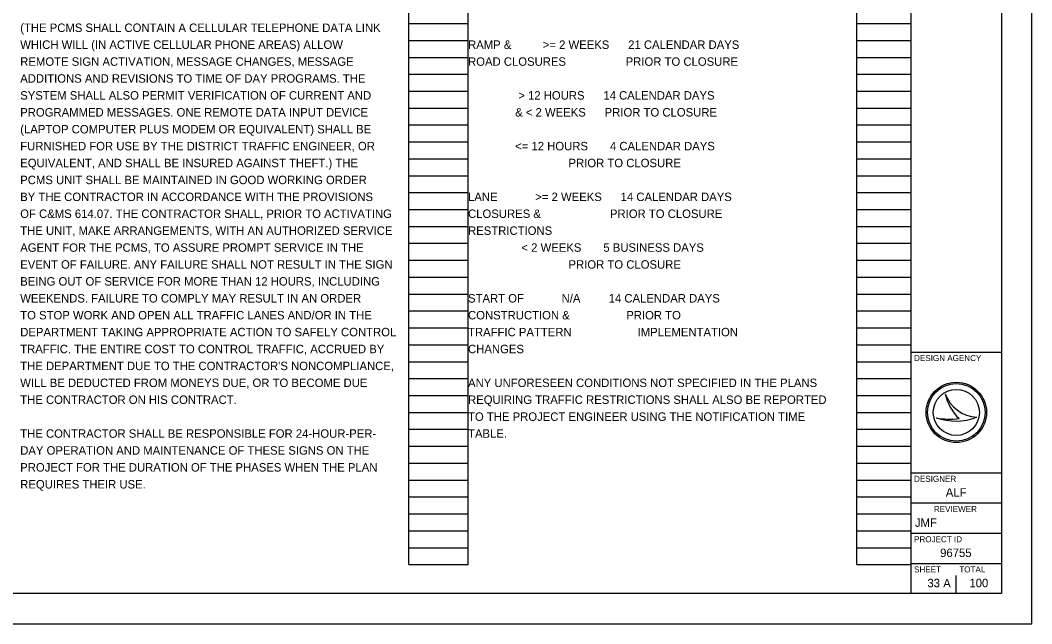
# Model space of a CAD drawing. Extents: x 0 to 34, y 0 to 22.
# Drawn here: x 17.24 to 34, y 0 to 9.99 of the extents above; entities that cross this region are included whole.
import ezdxf

# ---------------------------------------------------------------- set-up
doc = ezdxf.new("R2010")
doc.units = 0
for name, color, linetype in [('Default', 7, 'Continuous'), ('SH_Border', 7, 'Continuous'), ('SH_Cut_Line', 7, 'Continuous'), ('SH_Data', 7, 'Continuous'), ('SH_Text', 7, 'Continuous')]:
    doc.layers.add(name, color=color, linetype=linetype)

msp = doc.modelspace()

# ---------------------------------------------------------------- linework, layer by layer
at = {"layer": 'SH_Border'}
for p, q in [((32, 0.5), (32, 21.5)), ((32, 4.5), (33.5, 4.5)), ((32, 2.5), (33.5, 2.5)), ((32, 2), (33.5, 2)), ((32, 1.5), (33.5, 1.5)), ((32, 1), (33.5, 1))]:
    msp.add_line(p, q, dxfattribs=at)
msp.add_lwpolyline([(1.5, 21.5), (33.5, 21.5), (33.5, 0.5), (1.5, 0.5)], close=True, dxfattribs=at)
at = {"layer": 'SH_Cut_Line'}
msp.add_lwpolyline([(0, 0), (34, 0), (34, 22), (0, 22)], close=True, dxfattribs=at)
at = {"layer": 'SH_Data'}
for p, q in [((23.68, 0.98), (23.68, 21.14)), ((24.66, 0.98), (24.66, 21.14)), ((31.1, 0.98), (31.1, 21.14)), ((32, 0.98), (32, 21.14)), ((23.68, 9.94), (24.66, 9.94)), ((31.1, 9.94), (32, 9.94)), ((23.68, 9.66), (24.66, 9.66)), ((31.1, 9.66), (32, 9.66)), ((23.68, 9.38), (24.66, 9.38)), ((31.1, 9.38), (32, 9.38)), ((23.68, 9.1), (24.66, 9.1)), ((31.1, 9.1), (32, 9.1)), ((23.68, 8.82), (24.66, 8.82)), ((31.1, 8.82), (32, 8.82)), ((23.68, 8.54), (24.66, 8.54)), ((31.1, 8.54), (32, 8.54)), ((23.68, 8.26), (24.66, 8.26)), ((31.1, 8.26), (32, 8.26)), ((23.68, 7.98), (24.66, 7.98)), ((31.1, 7.98), (32, 7.98)), ((23.68, 7.7), (24.66, 7.7)), ((31.1, 7.7), (32, 7.7)), ((23.68, 7.42), (24.66, 7.42)), ((31.1, 7.42), (32, 7.42)), ((23.68, 7.14), (24.66, 7.14)), ((31.1, 7.14), (32, 7.14)), ((23.68, 6.86), (24.66, 6.86)), ((31.1, 6.86), (32, 6.86)), ((23.68, 6.58), (24.66, 6.58)), ((31.1, 6.58), (32, 6.58)), ((23.68, 6.3), (24.66, 6.3)), ((31.1, 6.3), (32, 6.3)), ((23.68, 6.02), (24.66, 6.02)), ((31.1, 6.02), (32, 6.02)), ((23.68, 5.74), (24.66, 5.74)), ((31.1, 5.74), (32, 5.74)), ((23.68, 5.46), (24.66, 5.46)), ((31.1, 5.46), (32, 5.46)), ((23.68, 5.18), (24.66, 5.18)), ((31.1, 5.18), (32, 5.18)), ((23.68, 4.9), (24.66, 4.9)), ((31.1, 4.9), (32, 4.9)), ((23.68, 4.62), (24.66, 4.62)), ((31.1, 4.62), (32, 4.62)), ((23.68, 4.34), (24.66, 4.34)), ((31.1, 4.34), (32, 4.34)), ((23.68, 4.06), (24.66, 4.06)), ((31.1, 4.06), (32, 4.06)), ((23.68, 3.78), (24.66, 3.78)), ((31.1, 3.78), (32, 3.78)), ((32.567, 3.81), (32.567, 3.81)), ((23.68, 3.5), (24.66, 3.5)), ((31.1, 3.5), (32, 3.5)), ((32.417, 3.41), (32.417, 3.41)), ((32.75, 3.5), (32.75, 3.5)), ((33.087, 3.419), (33.087, 3.419)), ((23.68, 3.22), (24.66, 3.22)), ((31.1, 3.22), (32, 3.22)), ((23.68, 2.94), (24.66, 2.94)), ((31.1, 2.94), (32, 2.94)), ((23.68, 2.66), (24.66, 2.66)), ((31.1, 2.66), (32, 2.66)), ((23.68, 2.38), (24.66, 2.38)), ((31.1, 2.38), (32, 2.38)), ((23.68, 2.1), (24.66, 2.1)), ((31.1, 2.1), (32, 2.1)), ((23.68, 1.82), (24.66, 1.82)), ((31.1, 1.82), (32, 1.82)), ((23.68, 1.54), (24.66, 1.54)), ((31.1, 1.54), (32, 1.54)), ((23.68, 1.26), (24.66, 1.26)), ((31.1, 1.26), (32, 1.26)), ((23.68, 0.98), (24.66, 0.98)), ((31.1, 0.98), (32, 0.98)), ((32.375, 0.675), (32.375, 0.675)), ((32.75, 0.5), (32.75, 0.8))]:
    msp.add_line(p, q, dxfattribs=at)
for radius in [0.5, 0.477, 0.477, 0.382]:
    msp.add_circle((32.75, 3.5), radius, dxfattribs=at)
for centre, radius, start, end in [((33.116, 3.998), 0.58, 198.9257, 198.9319), ((33.347, 3.97), 0.796, 191.6379, 191.6421), ((33.116, 3.998), 0.58, 198.9319, 267.1657), ((33.347, 3.97), 0.796, 191.6421, 226.0947), ((32.739, 4.37), 1.013, 251.4576, 290.0832), ((32.648, 4.654), 1.266, 259.4964, 259.4995), ((32.739, 4.37), 1.013, 251.4527, 251.4576), ((32.648, 4.654), 1.266, 259.4995, 276.6672)]:
    msp.add_arc(centre, radius, start, end, dxfattribs=at)

# ---------------------------------------------------------------- texts
at = {"layer": 'Default'}
msp.add_text('A', height=0.14, dxfattribs=at).set_placement((32.533, 0.602))
at = {"layer": 'SH_Data'}
for s, height, p in [('DESIGN AGENCY', 0.1, (32.05, 4.35)), ('DESIGNER', 0.1, (32.05, 2.35)), ('ALF', 0.14, (32.575, 2.105)), ('REVIEWER', 0.1, (32.378, 1.85)), ('JMF', 0.14, (32.064, 1.605)), ('PROJECT ID', 0.1, (32.05, 1.35)), ('96755', 0.14, (32.482, 1.105)), ('SHEET', 0.1, (32.05, 0.85)), ('TOTAL', 0.1, (32.8, 0.85)), ('33', 0.14, (32.271, 0.605)), ('100', 0.14, (32.967, 0.605))]:
    msp.add_text(s, height=height, dxfattribs=at).set_placement(p)
at = {"layer": 'SH_Text'}
for s, p in [('(THE PCMS SHALL CONTAIN A CELLULAR TELEPHONE DATA LINK', (17.24, 9.8)), ('WHICH WILL (IN ACTIVE CELLULAR PHONE AREAS) ALLOW', (17.24, 9.52)), ('RAMP &          >= 2 WEEKS      21 CALENDAR DAYS', (24.66, 9.52)), ('REMOTE SIGN ACTIVATION, MESSAGE CHANGES, MESSAGE', (17.24, 9.24)), ('ROAD CLOSURES                   PRIOR TO CLOSURE', (24.66, 9.24)), ('ADDITIONS AND REVISIONS TO TIME OF DAY PROGRAMS. THE', (17.24, 8.96)), ('SYSTEM SHALL ALSO PERMIT VERIFICATION OF CURRENT AND', (17.24, 8.68)), ('                > 12 HOURS      14 CALENDAR DAYS', (24.66, 8.68)), ('PROGRAMMED MESSAGES. ONE REMOTE DATA INPUT DEVICE', (17.24, 8.4)), ('               & < 2 WEEKS      PRIOR TO CLOSURE', (24.66, 8.4)), ('(LAPTOP COMPUTER PLUS MODEM OR EQUIVALENT) SHALL BE', (17.24, 8.12)), ('FURNISHED FOR USE BY THE DISTRICT TRAFFIC ENGINEER, OR', (17.24, 7.84)), ('               <= 12 HOURS       4 CALENDAR DAYS', (24.66, 7.84)), ('EQUIVALENT, AND SHALL BE INSURED AGAINST THEFT.) THE', (17.24, 7.56)), ('                                PRIOR TO CLOSURE', (24.66, 7.56)), ('PCMS UNIT SHALL BE MAINTAINED IN GOOD WORKING ORDER', (17.24, 7.28)), ('BY THE CONTRACTOR IN ACCORDANCE WITH THE PROVISIONS', (17.24, 7)), ('LANE            >= 2 WEEKS      14 CALENDAR DAYS', (24.66, 7)), ('OF C&MS 614.07. THE CONTRACTOR SHALL, PRIOR TO ACTIVATING', (17.24, 6.72)), ('CLOSURES &                      PRIOR TO CLOSURE', (24.66, 6.72)), ('THE UNIT, MAKE ARRANGEMENTS, WITH AN AUTHORIZED SERVICE', (17.24, 6.44)), ('RESTRICTIONS', (24.66, 6.44)), ('AGENT FOR THE PCMS, TO ASSURE PROMPT SERVICE IN THE', (17.24, 6.16)), ('                 < 2 WEEKS       5 BUSINESS DAYS', (24.66, 6.16)), ('EVENT OF FAILURE. ANY FAILURE SHALL NOT RESULT IN THE SIGN', (17.24, 5.88)), ('                                PRIOR TO CLOSURE', (24.66, 5.88)), ('BEING OUT OF SERVICE FOR MORE THAN 12 HOURS, INCLUDING', (17.24, 5.6)), ('WEEKENDS. FAILURE TO COMPLY MAY RESULT IN AN ORDER', (17.24, 5.32)), ('START OF            N/A         14 CALENDAR DAYS', (24.66, 5.32)), ('TO STOP WORK AND OPEN ALL TRAFFIC LANES AND/OR IN THE', (17.24, 5.04)), ('CONSTRUCTION &                  PRIOR TO', (24.66, 5.04)), ('DEPARTMENT TAKING APPROPRIATE ACTION TO SAFELY CONTROL', (17.24, 4.76)), ('TRAFFIC PATTERN                     IMPLEMENTATION', (24.66, 4.76)), ('TRAFFIC. THE ENTIRE COST TO CONTROL TRAFFIC, ACCRUED BY', (17.24, 4.48)), ('CHANGES', (24.66, 4.48)), ("THE DEPARTMENT DUE TO THE CONTRACTOR'S NONCOMPLIANCE,", (17.24, 4.2)), ('WILL BE DEDUCTED FROM MONEYS DUE, OR TO BECOME DUE', (17.24, 3.92)), ('ANY UNFORESEEN CONDITIONS NOT SPECIFIED IN THE PLANS', (24.66, 3.92)), ('THE CONTRACTOR ON HIS CONTRACT.', (17.24, 3.64)), ('REQUIRING TRAFFIC RESTRICTIONS SHALL ALSO BE REPORTED', (24.66, 3.64)), ('TO THE PROJECT ENGINEER USING THE NOTIFICATION TIME', (24.66, 3.36)), ('THE CONTRACTOR SHALL BE RESPONSIBLE FOR 24-HOUR-PER-', (17.24, 3.08)), ('TABLE.', (24.66, 3.08)), ('DAY OPERATION AND MAINTENANCE OF THESE SIGNS ON THE', (17.24, 2.8)), ('PROJECT FOR THE DURATION OF THE PHASES WHEN THE PLAN', (17.24, 2.52)), ('REQUIRES THEIR USE.', (17.24, 2.24))]:
    msp.add_text(s, height=0.14, dxfattribs=at).set_placement(p)

doc.saveas('drawing.dxf')
